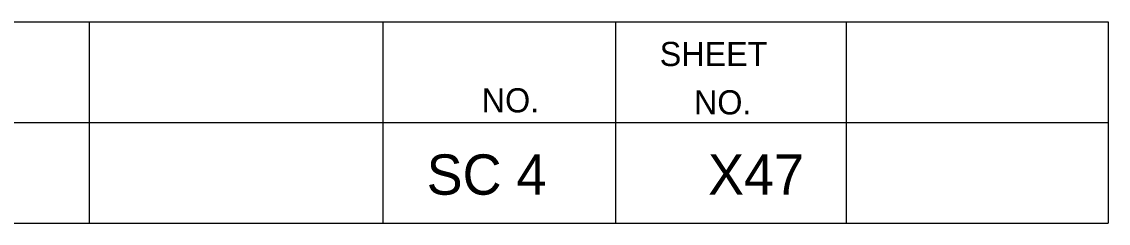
# Model space of a CAD drawing. Extents: x 1000 to 1162, y 999 to 8520.
# Drawn here: x 1148.08 to 1161.56, y 6390.05 to 6392.55 of the extents above; entities that cross this region are included whole.
import ezdxf

# ---------------------------------------------------------------- set-up
doc = ezdxf.new("R2010")
doc.units = 0
doc.layers.add('Level 20', color=7, linetype='Continuous')
doc.layers.add('Level 3', color=7, linetype='Continuous')

msp = doc.modelspace()

# ---------------------------------------------------------------- linework, layer by layer
at = {"layer": 'Level 3'}
for p, q in [((1133.055, 6392.546), (1161.555, 6392.546)), ((1133.055, 6392.546), (1161.555, 6392.546)), ((1133.055, 6392.546), (1161.555, 6392.546)), ((1133.055, 6392.546), (1161.555, 6392.546)), ((1133.055, 6392.546), (1161.555, 6392.546)), ((1133.055, 6392.546), (1161.555, 6392.546)), ((1133.055, 6392.546), (1161.555, 6392.546)), ((1133.055, 6392.546), (1161.555, 6392.546)), ((1133.055, 6392.546), (1161.555, 6392.546)), ((1133.055, 6392.546), (1161.555, 6392.546)), ((1133.055, 6392.546), (1161.555, 6392.546)), ((1133.055, 6392.546), (1161.555, 6392.546)), ((1133.055, 6392.546), (1161.555, 6392.546)), ((1133.055, 6392.546), (1161.555, 6392.546)), ((1133.055, 6392.546), (1161.555, 6392.546)), ((1133.055, 6392.546), (1161.555, 6392.546)), ((1133.055, 6392.546), (1161.555, 6392.546)), ((1133.055, 6392.546), (1161.555, 6392.546)), ((1133.055, 6392.546), (1161.555, 6392.546)), ((1133.055, 6392.546), (1161.555, 6392.546)), ((1133.055, 6392.546), (1161.555, 6392.546)), ((1133.055, 6392.546), (1161.555, 6392.546)), ((1133.055, 6392.546), (1161.555, 6392.546)), ((1133.055, 6392.546), (1161.555, 6392.546)), ((1133.055, 6392.546), (1161.555, 6392.546)), ((1133.055, 6392.546), (1161.555, 6392.546)), ((1133.055, 6392.546), (1161.555, 6392.546)), ((1133.055, 6392.546), (1161.555, 6392.546)), ((1133.055, 6392.546), (1161.555, 6392.546)), ((1133.055, 6392.546), (1161.555, 6392.546)), ((1133.055, 6392.546), (1161.555, 6392.546)), ((1133.055, 6392.546), (1161.555, 6392.546)), ((1133.055, 6392.546), (1161.555, 6392.546)), ((1133.055, 6392.546), (1161.555, 6392.546)), ((1133.055, 6392.546), (1161.555, 6392.546)), ((1133.055, 6392.546), (1161.555, 6392.546)), ((1133.055, 6392.546), (1161.555, 6392.546)), ((1133.055, 6392.546), (1161.555, 6392.546)), ((1133.055, 6392.546), (1161.555, 6392.546)), ((1133.055, 6392.546), (1161.555, 6392.546)), ((1133.055, 6392.546), (1161.555, 6392.546)), ((1133.055, 6392.546), (1161.555, 6392.546)), ((1133.055, 6392.546), (1161.555, 6392.546)), ((1133.055, 6392.546), (1161.555, 6392.546)), ((1133.055, 6392.546), (1161.555, 6392.546)), ((1148.913, 6392.546), (1148.913, 6390.046)), ((1148.913, 6392.546), (1148.913, 6390.046)), ((1148.913, 6392.546), (1148.913, 6390.046)), ((1148.913, 6392.546), (1148.913, 6390.046)), ((1148.913, 6392.546), (1148.913, 6390.046)), ((1148.913, 6392.546), (1148.913, 6390.046)), ((1148.913, 6392.546), (1148.913, 6390.046)), ((1148.913, 6392.546), (1148.913, 6390.046)), ((1148.913, 6392.546), (1148.913, 6390.046)), ((1148.913, 6392.546), (1148.913, 6390.046)), ((1148.913, 6392.546), (1148.913, 6390.046)), ((1148.913, 6392.546), (1148.913, 6390.046)), ((1148.913, 6392.546), (1148.913, 6390.046)), ((1148.913, 6392.546), (1148.913, 6390.046)), ((1148.913, 6392.546), (1148.913, 6390.046)), ((1148.913, 6392.546), (1148.913, 6390.046)), ((1148.913, 6392.546), (1148.913, 6390.046)), ((1148.913, 6392.546), (1148.913, 6390.046)), ((1148.913, 6392.546), (1148.913, 6390.046)), ((1148.913, 6392.546), (1148.913, 6390.046)), ((1148.913, 6392.546), (1148.913, 6390.046)), ((1148.913, 6392.546), (1148.913, 6390.046)), ((1148.913, 6392.546), (1148.913, 6390.046)), ((1148.913, 6392.546), (1148.913, 6390.046)), ((1148.913, 6392.546), (1148.913, 6390.046)), ((1148.913, 6392.546), (1148.913, 6390.046)), ((1148.913, 6392.546), (1148.913, 6390.046)), ((1148.913, 6392.546), (1148.913, 6390.046)), ((1148.913, 6392.546), (1148.913, 6390.046)), ((1148.913, 6392.546), (1148.913, 6390.046)), ((1148.913, 6392.546), (1148.913, 6390.046)), ((1148.913, 6392.546), (1148.913, 6390.046)), ((1148.913, 6392.546), (1148.913, 6390.046)), ((1148.913, 6392.546), (1148.913, 6390.046)), ((1148.913, 6392.546), (1148.913, 6390.046)), ((1148.913, 6392.546), (1148.913, 6390.046)), ((1148.913, 6392.546), (1148.913, 6390.046)), ((1148.913, 6392.546), (1148.913, 6390.046)), ((1148.913, 6392.546), (1148.913, 6390.046)), ((1148.913, 6392.546), (1148.913, 6390.046)), ((1148.913, 6392.546), (1148.913, 6390.046)), ((1148.913, 6392.546), (1148.913, 6390.046)), ((1148.913, 6392.546), (1148.913, 6390.046)), ((1148.913, 6392.546), (1148.913, 6390.046)), ((1148.913, 6392.546), (1148.913, 6390.046)), ((1152.554, 6392.546), (1152.554, 6390.046)), ((1152.554, 6392.546), (1152.554, 6390.046)), ((1152.554, 6392.546), (1152.554, 6390.046)), ((1152.554, 6392.546), (1152.554, 6390.046)), ((1152.554, 6392.546), (1152.554, 6390.046)), ((1152.554, 6392.546), (1152.554, 6390.046)), ((1152.554, 6392.546), (1152.554, 6390.046)), ((1152.554, 6392.546), (1152.554, 6390.046)), ((1152.554, 6392.546), (1152.554, 6390.046)), ((1152.554, 6392.546), (1152.554, 6390.046)), ((1152.554, 6392.546), (1152.554, 6390.046)), ((1152.554, 6392.546), (1152.554, 6390.046)), ((1152.554, 6392.546), (1152.554, 6390.046)), ((1152.554, 6392.546), (1152.554, 6390.046)), ((1152.554, 6392.546), (1152.554, 6390.046)), ((1152.554, 6392.546), (1152.554, 6390.046)), ((1152.554, 6392.546), (1152.554, 6390.046)), ((1152.554, 6392.546), (1152.554, 6390.046)), ((1152.554, 6392.546), (1152.554, 6390.046)), ((1152.554, 6392.546), (1152.554, 6390.046)), ((1152.554, 6392.546), (1152.554, 6390.046)), ((1152.554, 6392.546), (1152.554, 6390.046)), ((1152.554, 6392.546), (1152.554, 6390.046)), ((1152.554, 6392.546), (1152.554, 6390.046)), ((1152.554, 6392.546), (1152.554, 6390.046)), ((1152.554, 6392.546), (1152.554, 6390.046)), ((1152.554, 6392.546), (1152.554, 6390.046)), ((1152.554, 6392.546), (1152.554, 6390.046)), ((1152.554, 6392.546), (1152.554, 6390.046)), ((1152.554, 6392.546), (1152.554, 6390.046)), ((1152.554, 6392.546), (1152.554, 6390.046)), ((1152.554, 6392.546), (1152.554, 6390.046)), ((1152.554, 6392.546), (1152.554, 6390.046)), ((1152.554, 6392.546), (1152.554, 6390.046)), ((1152.554, 6392.546), (1152.554, 6390.046)), ((1152.554, 6392.546), (1152.554, 6390.046)), ((1152.554, 6392.546), (1152.554, 6390.046)), ((1152.554, 6392.546), (1152.554, 6390.046)), ((1152.554, 6392.546), (1152.554, 6390.046)), ((1152.554, 6392.546), (1152.554, 6390.046)), ((1152.554, 6392.546), (1152.554, 6390.046)), ((1152.554, 6392.546), (1152.554, 6390.046)), ((1152.554, 6392.546), (1152.554, 6390.046)), ((1152.554, 6392.546), (1152.554, 6390.046)), ((1152.554, 6392.546), (1152.554, 6390.046)), ((1155.44, 6392.546), (1155.44, 6390.046)), ((1155.44, 6392.546), (1155.44, 6390.046)), ((1155.44, 6392.546), (1155.44, 6390.046)), ((1155.44, 6392.546), (1155.44, 6390.046)), ((1155.44, 6392.546), (1155.44, 6390.046)), ((1155.44, 6392.546), (1155.44, 6390.046)), ((1155.44, 6392.546), (1155.44, 6390.046)), ((1155.44, 6392.546), (1155.44, 6390.046)), ((1155.44, 6392.546), (1155.44, 6390.046)), ((1155.44, 6392.546), (1155.44, 6390.046)), ((1155.44, 6392.546), (1155.44, 6390.046)), ((1155.44, 6392.546), (1155.44, 6390.046)), ((1155.44, 6392.546), (1155.44, 6390.046)), ((1155.44, 6392.546), (1155.44, 6390.046)), ((1155.44, 6392.546), (1155.44, 6390.046)), ((1155.44, 6392.546), (1155.44, 6390.046)), ((1155.44, 6392.546), (1155.44, 6390.046)), ((1155.44, 6392.546), (1155.44, 6390.046)), ((1155.44, 6392.546), (1155.44, 6390.046)), ((1155.44, 6392.546), (1155.44, 6390.046)), ((1155.44, 6392.546), (1155.44, 6390.046)), ((1155.44, 6392.546), (1155.44, 6390.046)), ((1155.44, 6392.546), (1155.44, 6390.046)), ((1155.44, 6392.546), (1155.44, 6390.046)), ((1155.44, 6392.546), (1155.44, 6390.046)), ((1155.44, 6392.546), (1155.44, 6390.046)), ((1155.44, 6392.546), (1155.44, 6390.046)), ((1155.44, 6392.546), (1155.44, 6390.046)), ((1155.44, 6392.546), (1155.44, 6390.046)), ((1155.44, 6392.546), (1155.44, 6390.046)), ((1155.44, 6392.546), (1155.44, 6390.046)), ((1155.44, 6392.546), (1155.44, 6390.046)), ((1155.44, 6392.546), (1155.44, 6390.046)), ((1155.44, 6392.546), (1155.44, 6390.046)), ((1155.44, 6392.546), (1155.44, 6390.046)), ((1155.44, 6392.546), (1155.44, 6390.046)), ((1155.44, 6392.546), (1155.44, 6390.046)), ((1155.44, 6392.546), (1155.44, 6390.046)), ((1155.44, 6392.546), (1155.44, 6390.046)), ((1155.44, 6392.546), (1155.44, 6390.046)), ((1155.44, 6392.546), (1155.44, 6390.046)), ((1155.44, 6392.546), (1155.44, 6390.046)), ((1155.44, 6392.546), (1155.44, 6390.046)), ((1155.44, 6392.546), (1155.44, 6390.046)), ((1155.44, 6392.546), (1155.44, 6390.046)), ((1158.305, 6392.546), (1158.305, 6390.046)), ((1158.305, 6392.546), (1158.305, 6390.046)), ((1158.305, 6392.546), (1158.305, 6390.046)), ((1158.305, 6392.546), (1158.305, 6390.046)), ((1158.305, 6392.546), (1158.305, 6390.046)), ((1158.305, 6392.546), (1158.305, 6390.046)), ((1158.305, 6392.546), (1158.305, 6390.046)), ((1158.305, 6392.546), (1158.305, 6390.046)), ((1158.305, 6392.546), (1158.305, 6390.046)), ((1158.305, 6392.546), (1158.305, 6390.046)), ((1158.305, 6392.546), (1158.305, 6390.046)), ((1158.305, 6392.546), (1158.305, 6390.046)), ((1158.305, 6392.546), (1158.305, 6390.046)), ((1158.305, 6392.546), (1158.305, 6390.046)), ((1158.305, 6392.546), (1158.305, 6390.046)), ((1158.305, 6392.546), (1158.305, 6390.046)), ((1158.305, 6392.546), (1158.305, 6390.046)), ((1158.305, 6392.546), (1158.305, 6390.046)), ((1158.305, 6392.546), (1158.305, 6390.046)), ((1158.305, 6392.546), (1158.305, 6390.046)), ((1158.305, 6392.546), (1158.305, 6390.046)), ((1158.305, 6392.546), (1158.305, 6390.046)), ((1158.305, 6392.546), (1158.305, 6390.046)), ((1158.305, 6392.546), (1158.305, 6390.046)), ((1158.305, 6392.546), (1158.305, 6390.046)), ((1158.305, 6392.546), (1158.305, 6390.046)), ((1158.305, 6392.546), (1158.305, 6390.046)), ((1158.305, 6392.546), (1158.305, 6390.046)), ((1158.305, 6392.546), (1158.305, 6390.046)), ((1158.305, 6392.546), (1158.305, 6390.046)), ((1158.305, 6392.546), (1158.305, 6390.046)), ((1158.305, 6392.546), (1158.305, 6390.046)), ((1158.305, 6392.546), (1158.305, 6390.046)), ((1158.305, 6392.546), (1158.305, 6390.046)), ((1158.305, 6392.546), (1158.305, 6390.046)), ((1158.305, 6392.546), (1158.305, 6390.046)), ((1158.305, 6392.546), (1158.305, 6390.046)), ((1158.305, 6392.546), (1158.305, 6390.046)), ((1158.305, 6392.546), (1158.305, 6390.046)), ((1158.305, 6392.546), (1158.305, 6390.046)), ((1158.305, 6392.546), (1158.305, 6390.046)), ((1158.305, 6392.546), (1158.305, 6390.046)), ((1158.305, 6392.546), (1158.305, 6390.046)), ((1158.305, 6392.546), (1158.305, 6390.046)), ((1158.305, 6392.546), (1158.305, 6390.046)), ((1161.555, 6392.546), (1161.555, 6390.046)), ((1161.555, 6392.546), (1161.555, 6390.046)), ((1161.555, 6392.546), (1161.555, 6390.046)), ((1161.555, 6392.546), (1161.555, 6390.046)), ((1161.555, 6392.546), (1161.555, 6390.046)), ((1161.555, 6392.546), (1161.555, 6390.046)), ((1161.555, 6392.546), (1161.555, 6390.046)), ((1161.555, 6392.546), (1161.555, 6390.046)), ((1161.555, 6392.546), (1161.555, 6390.046)), ((1161.555, 6392.546), (1161.555, 6390.046)), ((1161.555, 6392.546), (1161.555, 6390.046)), ((1161.555, 6392.546), (1161.555, 6390.046)), ((1161.555, 6392.546), (1161.555, 6390.046)), ((1161.555, 6392.546), (1161.555, 6390.046)), ((1161.555, 6392.546), (1161.555, 6390.046)), ((1161.555, 6392.546), (1161.555, 6390.046)), ((1161.555, 6392.546), (1161.555, 6390.046)), ((1161.555, 6392.546), (1161.555, 6390.046)), ((1161.555, 6392.546), (1161.555, 6390.046)), ((1161.555, 6392.546), (1161.555, 6390.046)), ((1161.555, 6392.546), (1161.555, 6390.046)), ((1161.555, 6392.546), (1161.555, 6390.046)), ((1161.555, 6392.546), (1161.555, 6390.046)), ((1161.555, 6392.546), (1161.555, 6390.046)), ((1161.555, 6392.546), (1161.555, 6390.046)), ((1161.555, 6392.546), (1161.555, 6390.046)), ((1161.555, 6392.546), (1161.555, 6390.046)), ((1161.555, 6392.546), (1161.555, 6390.046)), ((1161.555, 6392.546), (1161.555, 6390.046)), ((1161.555, 6392.546), (1161.555, 6390.046)), ((1161.555, 6392.546), (1161.555, 6390.046)), ((1161.555, 6392.546), (1161.555, 6390.046)), ((1161.555, 6392.546), (1161.555, 6390.046)), ((1161.555, 6392.546), (1161.555, 6390.046)), ((1161.555, 6392.546), (1161.555, 6390.046)), ((1161.555, 6392.546), (1161.555, 6390.046)), ((1161.555, 6392.546), (1161.555, 6390.046)), ((1161.555, 6392.546), (1161.555, 6390.046)), ((1161.555, 6392.546), (1161.555, 6390.046)), ((1161.555, 6392.546), (1161.555, 6390.046)), ((1161.555, 6392.546), (1161.555, 6390.046)), ((1161.555, 6392.546), (1161.555, 6390.046)), ((1161.555, 6392.546), (1161.555, 6390.046)), ((1161.555, 6392.546), (1161.555, 6390.046)), ((1161.555, 6392.546), (1161.555, 6390.046)), ((1133.055, 6391.296), (1161.555, 6391.296)), ((1133.055, 6391.296), (1161.555, 6391.296)), ((1133.055, 6391.296), (1161.555, 6391.296)), ((1133.055, 6391.296), (1161.555, 6391.296)), ((1133.055, 6391.296), (1161.555, 6391.296)), ((1133.055, 6391.296), (1161.555, 6391.296)), ((1133.055, 6391.296), (1161.555, 6391.296)), ((1133.055, 6391.296), (1161.555, 6391.296)), ((1133.055, 6391.296), (1161.555, 6391.296)), ((1133.055, 6391.296), (1161.555, 6391.296)), ((1133.055, 6391.296), (1161.555, 6391.296)), ((1133.055, 6391.296), (1161.555, 6391.296)), ((1133.055, 6391.296), (1161.555, 6391.296)), ((1133.055, 6391.296), (1161.555, 6391.296)), ((1133.055, 6391.296), (1161.555, 6391.296)), ((1133.055, 6391.296), (1161.555, 6391.296)), ((1133.055, 6391.296), (1161.555, 6391.296)), ((1133.055, 6391.296), (1161.555, 6391.296)), ((1133.055, 6391.296), (1161.555, 6391.296)), ((1133.055, 6391.296), (1161.555, 6391.296)), ((1133.055, 6391.296), (1161.555, 6391.296)), ((1133.055, 6391.296), (1161.555, 6391.296)), ((1133.055, 6391.296), (1161.555, 6391.296)), ((1133.055, 6391.296), (1161.555, 6391.296)), ((1133.055, 6391.296), (1161.555, 6391.296)), ((1133.055, 6391.296), (1161.555, 6391.296)), ((1133.055, 6391.296), (1161.555, 6391.296)), ((1133.055, 6391.296), (1161.555, 6391.296)), ((1133.055, 6391.296), (1161.555, 6391.296)), ((1133.055, 6391.296), (1161.555, 6391.296)), ((1133.055, 6391.296), (1161.555, 6391.296)), ((1133.055, 6391.296), (1161.555, 6391.296)), ((1133.055, 6391.296), (1161.555, 6391.296)), ((1133.055, 6391.296), (1161.555, 6391.296)), ((1133.055, 6391.296), (1161.555, 6391.296)), ((1133.055, 6391.296), (1161.555, 6391.296)), ((1133.055, 6391.296), (1161.555, 6391.296)), ((1133.055, 6391.296), (1161.555, 6391.296)), ((1133.055, 6391.296), (1161.555, 6391.296)), ((1133.055, 6391.296), (1161.555, 6391.296)), ((1133.055, 6391.296), (1161.555, 6391.296)), ((1133.055, 6391.296), (1161.555, 6391.296)), ((1133.055, 6391.296), (1161.555, 6391.296)), ((1133.055, 6391.296), (1161.555, 6391.296)), ((1133.055, 6391.296), (1161.555, 6391.296)), ((1133.055, 6390.046), (1161.555, 6390.046)), ((1133.055, 6390.046), (1161.555, 6390.046)), ((1133.055, 6390.046), (1161.555, 6390.046)), ((1133.055, 6390.046), (1161.555, 6390.046)), ((1133.055, 6390.046), (1161.555, 6390.046)), ((1133.055, 6390.046), (1161.555, 6390.046)), ((1133.055, 6390.046), (1161.555, 6390.046)), ((1133.055, 6390.046), (1161.555, 6390.046)), ((1133.055, 6390.046), (1161.555, 6390.046)), ((1133.055, 6390.046), (1161.555, 6390.046)), ((1133.055, 6390.046), (1161.555, 6390.046)), ((1133.055, 6390.046), (1161.555, 6390.046)), ((1133.055, 6390.046), (1161.555, 6390.046)), ((1133.055, 6390.046), (1161.555, 6390.046)), ((1133.055, 6390.046), (1161.555, 6390.046)), ((1133.055, 6390.046), (1161.555, 6390.046)), ((1133.055, 6390.046), (1161.555, 6390.046)), ((1133.055, 6390.046), (1161.555, 6390.046)), ((1133.055, 6390.046), (1161.555, 6390.046)), ((1133.055, 6390.046), (1161.555, 6390.046)), ((1133.055, 6390.046), (1161.555, 6390.046)), ((1133.055, 6390.046), (1161.555, 6390.046)), ((1133.055, 6390.046), (1161.555, 6390.046)), ((1133.055, 6390.046), (1161.555, 6390.046)), ((1133.055, 6390.046), (1161.555, 6390.046)), ((1133.055, 6390.046), (1161.555, 6390.046)), ((1133.055, 6390.046), (1161.555, 6390.046)), ((1133.055, 6390.046), (1161.555, 6390.046)), ((1133.055, 6390.046), (1161.555, 6390.046)), ((1133.055, 6390.046), (1161.555, 6390.046)), ((1133.055, 6390.046), (1161.555, 6390.046)), ((1133.055, 6390.046), (1161.555, 6390.046)), ((1133.055, 6390.046), (1161.555, 6390.046)), ((1133.055, 6390.046), (1161.555, 6390.046)), ((1133.055, 6390.046), (1161.555, 6390.046)), ((1133.055, 6390.046), (1161.555, 6390.046)), ((1133.055, 6390.046), (1161.555, 6390.046)), ((1133.055, 6390.046), (1161.555, 6390.046)), ((1133.055, 6390.046), (1161.555, 6390.046)), ((1133.055, 6390.046), (1161.555, 6390.046)), ((1133.055, 6390.046), (1161.555, 6390.046)), ((1133.055, 6390.046), (1161.555, 6390.046)), ((1133.055, 6390.046), (1161.555, 6390.046)), ((1133.055, 6390.046), (1161.555, 6390.046)), ((1133.055, 6390.046), (1161.555, 6390.046))]:
    msp.add_line(p, q, dxfattribs=at)

# ---------------------------------------------------------------- texts
at = {"layer": 'Level 20'}
for s, p in [('SC 4', (1153.099, 6390.4)), ('X47', (1156.59, 6390.4))]:
    msp.add_text(s, height=0.5, dxfattribs=at).set_placement(p)
at = {"layer": 'Level 3'}
for s, p in [('SHEET', (1155.99, 6391.996)), ('SHEET', (1155.99, 6391.996)), ('SHEET', (1155.99, 6391.996)), ('SHEET', (1155.99, 6391.996)), ('SHEET', (1155.99, 6391.996)), ('SHEET', (1155.99, 6391.996)), ('SHEET', (1155.99, 6391.996)), ('SHEET', (1155.99, 6391.996)), ('SHEET', (1155.99, 6391.996)), ('SHEET', (1155.99, 6391.996)), ('SHEET', (1155.99, 6391.996)), ('SHEET', (1155.99, 6391.996)), ('SHEET', (1155.99, 6391.996)), ('SHEET', (1155.99, 6391.996)), ('SHEET', (1155.99, 6391.996)), ('SHEET', (1155.99, 6391.996)), ('SHEET', (1155.99, 6391.996)), ('SHEET', (1155.99, 6391.996)), ('SHEET', (1155.99, 6391.996)), ('SHEET', (1155.99, 6391.996)), ('SHEET', (1155.99, 6391.996)), ('SHEET', (1155.99, 6391.996)), ('SHEET', (1155.99, 6391.996)), ('SHEET', (1155.99, 6391.996)), ('SHEET', (1155.99, 6391.996)), ('SHEET', (1155.99, 6391.996)), ('SHEET', (1155.99, 6391.996)), ('SHEET', (1155.99, 6391.996)), ('SHEET', (1155.99, 6391.996)), ('SHEET', (1155.99, 6391.996)), ('SHEET', (1155.99, 6391.996)), ('SHEET', (1155.99, 6391.996)), ('SHEET', (1155.99, 6391.996)), ('SHEET', (1155.99, 6391.996)), ('SHEET', (1155.99, 6391.996)), ('SHEET', (1155.99, 6391.996)), ('SHEET', (1155.99, 6391.996)), ('SHEET', (1155.99, 6391.996)), ('SHEET', (1155.99, 6391.996)), ('SHEET', (1155.99, 6391.996)), ('SHEET', (1155.99, 6391.996)), ('SHEET', (1155.99, 6391.996)), ('SHEET', (1155.99, 6391.996)), ('SHEET', (1155.99, 6391.996)), ('SHEET', (1155.99, 6391.996)), ('NO.', (1153.782, 6391.421)), ('NO.', (1153.782, 6391.421)), ('NO.', (1153.782, 6391.421)), ('NO.', (1153.782, 6391.421)), ('NO.', (1153.782, 6391.421)), ('NO.', (1153.782, 6391.421)), ('NO.', (1153.782, 6391.421)), ('NO.', (1153.782, 6391.421)), ('NO.', (1153.782, 6391.421)), ('NO.', (1153.782, 6391.421)), ('NO.', (1153.782, 6391.421)), ('NO.', (1153.782, 6391.421)), ('NO.', (1153.782, 6391.421)), ('NO.', (1153.782, 6391.421)), ('NO.', (1153.782, 6391.421)), ('NO.', (1153.782, 6391.421)), ('NO.', (1153.782, 6391.421)), ('NO.', (1153.782, 6391.421)), ('NO.', (1153.782, 6391.421)), ('NO.', (1153.782, 6391.421)), ('NO.', (1153.782, 6391.421)), ('NO.', (1153.782, 6391.421)), ('NO.', (1153.782, 6391.421)), ('NO.', (1153.782, 6391.421)), ('NO.', (1153.782, 6391.421)), ('NO.', (1153.782, 6391.421)), ('NO.', (1153.782, 6391.421)), ('NO.', (1153.782, 6391.421)), ('NO.', (1153.782, 6391.421)), ('NO.', (1153.782, 6391.421)), ('NO.', (1153.782, 6391.421)), ('NO.', (1153.782, 6391.421)), ('NO.', (1153.782, 6391.421)), ('NO.', (1153.782, 6391.421)), ('NO.', (1153.782, 6391.421)), ('NO.', (1153.782, 6391.421)), ('NO.', (1153.782, 6391.421)), ('NO.', (1153.782, 6391.421)), ('NO.', (1153.782, 6391.421)), ('NO.', (1153.782, 6391.421)), ('NO.', (1153.782, 6391.421)), ('NO.', (1153.782, 6391.421)), ('NO.', (1153.782, 6391.421)), ('NO.', (1153.782, 6391.421)), ('NO.', (1153.782, 6391.421)), ('NO.', (1156.415, 6391.396)), ('NO.', (1156.415, 6391.396)), ('NO.', (1156.415, 6391.396)), ('NO.', (1156.415, 6391.396)), ('NO.', (1156.415, 6391.396)), ('NO.', (1156.415, 6391.396)), ('NO.', (1156.415, 6391.396)), ('NO.', (1156.415, 6391.396)), ('NO.', (1156.415, 6391.396)), ('NO.', (1156.415, 6391.396)), ('NO.', (1156.415, 6391.396)), ('NO.', (1156.415, 6391.396)), ('NO.', (1156.415, 6391.396)), ('NO.', (1156.415, 6391.396)), ('NO.', (1156.415, 6391.396)), ('NO.', (1156.415, 6391.396)), ('NO.', (1156.415, 6391.396)), ('NO.', (1156.415, 6391.396)), ('NO.', (1156.415, 6391.396)), ('NO.', (1156.415, 6391.396)), ('NO.', (1156.415, 6391.396)), ('NO.', (1156.415, 6391.396)), ('NO.', (1156.415, 6391.396)), ('NO.', (1156.415, 6391.396)), ('NO.', (1156.415, 6391.396)), ('NO.', (1156.415, 6391.396)), ('NO.', (1156.415, 6391.396)), ('NO.', (1156.415, 6391.396)), ('NO.', (1156.415, 6391.396)), ('NO.', (1156.415, 6391.396)), ('NO.', (1156.415, 6391.396)), ('NO.', (1156.415, 6391.396)), ('NO.', (1156.415, 6391.396)), ('NO.', (1156.415, 6391.396)), ('NO.', (1156.415, 6391.396)), ('NO.', (1156.415, 6391.396)), ('NO.', (1156.415, 6391.396)), ('NO.', (1156.415, 6391.396)), ('NO.', (1156.415, 6391.396)), ('NO.', (1156.415, 6391.396)), ('NO.', (1156.415, 6391.396)), ('NO.', (1156.415, 6391.396)), ('NO.', (1156.415, 6391.396)), ('NO.', (1156.415, 6391.396)), ('NO.', (1156.415, 6391.396))]:
    msp.add_text(s, height=0.3, dxfattribs=at).set_placement(p)

doc.saveas('drawing.dxf')
